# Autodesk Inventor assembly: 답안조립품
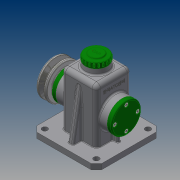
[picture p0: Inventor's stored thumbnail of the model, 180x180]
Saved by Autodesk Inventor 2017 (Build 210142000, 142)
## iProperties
Part Number: 답안조립품
Material: 일반
Document SubType Name: Assembly
Designer: 20
Author: 20
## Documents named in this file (14)
- C:\Users\20\Desktop\470818V1005\답안조립품.iam
- C:\Users\20\Desktop\470818V1005\본체.ipt
- C:\Users\20\Desktop\470818V1005\상부캡.ipt
- C:\Users\20\Desktop\470818V1005\뒤커버.ipt
- C:\Users\20\Desktop\470818V1005\볼트 M4 x 10.ipt
- C:\Users\20\Desktop\470818V1005\앞커버.ipt
- C:\Users\20\Desktop\470818V1005\베어링 15 x 35 x 11.ipt
- C:\Users\20\Desktop\470818V1005\축.ipt
- C:\Users\20\Desktop\470818V1005\멈춤링 15 x 1.ipt
- C:\Users\20\Desktop\470818V1005\오일실 15 25 7.ipt
- C:\Users\20\Desktop\470818V1005\키 5 x 5 x 14.ipt
- C:\Users\20\Desktop\470818V1005\V-벨트풀리.ipt
- C:\Users\20\Desktop\470818V1005\와셔.ipt
- C:\Users\20\Desktop\470818V1005\볼트 M6 x 12.ipt
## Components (1 placed, 1 different names)
1. V-벨트풀리:1 — 플러쉬:1
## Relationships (1: Flush 1)
- 플러쉬:1 [Flush]: V-벨트풀리:1
